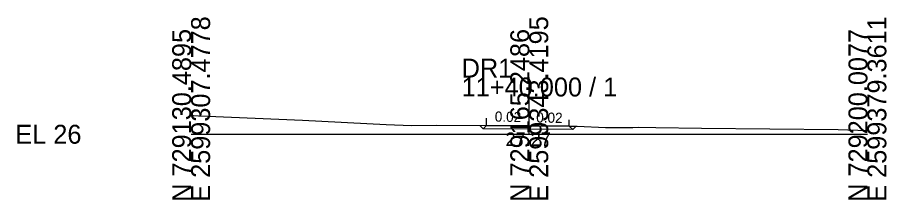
# Model space of a CAD drawing. Extents: x -26 to 1162, y -10 to 9515.
# Drawn here: x -25.7 to 102.8, y 6990.3 to 7017.3 of the extents above; entities that cross this region are included whole.
import ezdxf

# ---------------------------------------------------------------- set-up
doc = ezdxf.new("R2010")
doc.units = 0
for name, color, linetype in [('Exist Cross Section Cell', 7, 'Continuous'), ('Exist XS Center Line Elevation Label', 7, 'Continuous'), ('Exist XS Ground Line', 7, 'Continuous'), ('Prop XS Dump Level', 7, 'Continuous'), ('Prop XS EOT Tick Mark', 7, 'Continuous'), ('Prop XS Finish Grade Pavement', 7, 'Continuous'), ('Prop XS Pvmt Edge Slope', 7, 'Continuous'), ('Prop XS SE Text', 7, 'Continuous'), ('Prop XS Subgrade Earthwork', 7, 'Continuous')]:
    doc.layers.add(name, color=color, linetype=linetype)

msp = doc.modelspace()

# ---------------------------------------------------------------- linework, layer by layer
at = {"layer": 'Exist Cross Section Cell'}
for p, q in [((50, 7000), (50, 7008.4)), ((0, 7000), (50, 7000)), ((50, 7000), (100, 7000))]:
    msp.add_line(p, q, dxfattribs=at)
at = {"layer": 'Exist XS Ground Line'}
msp.add_lwpolyline([(0, 7002.8), (0.37, 7002.78), (1.1, 7002.75), (2.45, 7002.7), (16.49, 7002.07), (28.86, 7001.45), (32.59, 7001.32), (36.29, 7001.33), (43.7, 7001.31), (50, 7001.27), (53.56, 7001.25), (55.92, 7001.22), (57.06, 7001.18), (61.28, 7001.02), (65.29, 7001.01), (66.15, 7001.03), (68.69, 7001), (75.47, 7000.89), (95.67, 7000.71), (100, 7000.55)], dxfattribs=at)
at = {"layer": 'Prop XS Dump Level'}
for p, q in [((50, 7001.27), (43.68, 7001.31)), ((43.68, 7001.31), (50, 7001.27)), ((55.91, 7001.22), (50, 7001.27)), ((50, 7001.27), (55.91, 7001.22))]:
    msp.add_line(p, q, dxfattribs=at)
at = {"layer": 'Prop XS EOT Tick Mark'}
for p, q in [((43.68, 7001.31), (43.68, 7002.4)), ((55.91, 7001.22), (55.91, 7002.15))]:
    msp.add_line(p, q, dxfattribs=at)
at = {"layer": 'Prop XS Finish Grade Pavement'}
for p, q in [((43.68, 7001.31), (50, 7001.27)), ((50, 7001.27), (55.91, 7001.22))]:
    msp.add_line(p, q, dxfattribs=at)
at = {"layer": 'Prop XS Pvmt Edge Slope'}
for p, q in [((42.7, 7001.32), (43.19, 7000.82)), ((43.68, 7001.31), (43.19, 7000.82)), ((55.91, 7001.22), (56.42, 7000.71)), ((56.93, 7001.18), (56.42, 7000.71))]:
    msp.add_line(p, q, dxfattribs=at)
at = {"layer": 'Prop XS Subgrade Earthwork'}
for p, q in [((43.19, 7000.82), (42.7, 7001.32)), ((56.93, 7001.18), (56.42, 7000.71)), ((50, 7000.77), (43.19, 7000.82)), ((56.42, 7000.71), (50, 7000.77))]:
    msp.add_line(p, q, dxfattribs=at)

# ---------------------------------------------------------------- texts
at = {"layer": 'Exist Cross Section Cell'}
for s, p in [('E 2599307.4778', (2.8, 6990)), ('E 2599343.4195', (52.8, 6990)), ('E 2599379.3611', (102.8, 6990)), ('N 729130.4895', (0, 6990)), ('N 729165.2486', (50, 6990)), ('N 729200.0077', (100, 6990))]:
    msp.add_text(s, height=2.8, rotation=90, dxfattribs=at).set_placement(p)
for s, p in [('DR1', (40, 7008.4)), ('11+40.000 / 1', (40, 7005.6)), ('EL 26', (-26, 6998.6))]:
    msp.add_text(s, height=2.8, dxfattribs=at).set_placement(p)
at = {"layer": 'Exist XS Center Line Elevation Label'}
msp.add_text('27.27', height=2, dxfattribs=at).set_placement((46.49, 6998.27))
at = {"layer": 'Prop XS SE Text'}
for p in [(44.89, 7001.88), (51.01, 7001.75)]:
    msp.add_text('0.02', height=1.5, rotation=358.8542, dxfattribs=at).set_placement(p)

doc.saveas('drawing.dxf')
